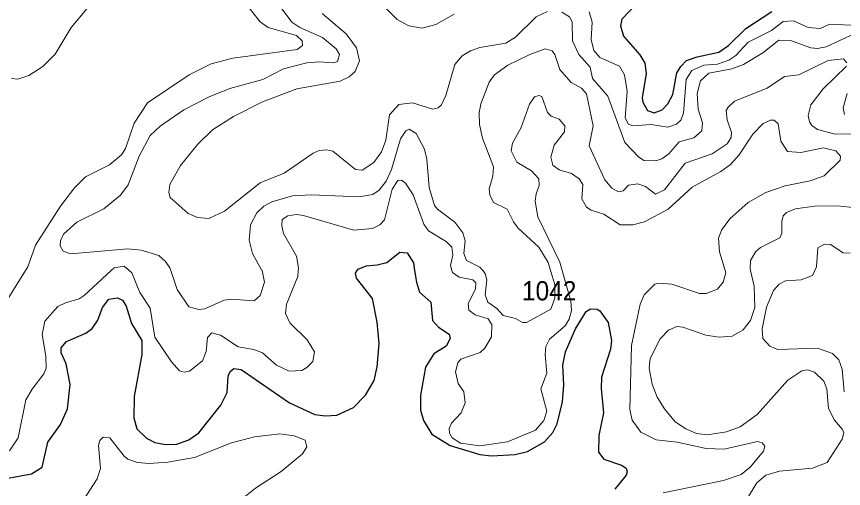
# Model space of a CAD drawing. Extents: x 473.9 to 500, y 7733.1 to 7760.8.
# Drawn here: x 479.07 to 482.505, y 7736.165 to 7738.123 of the extents above; entities that cross this region are included whole.
import ezdxf

# ---------------------------------------------------------------- set-up
doc = ezdxf.new("R2010")
doc.units = 0
doc.header["$LTSCALE"] = 0.032
doc.layers.add('1', color=7, linetype='Continuous', lineweight=25)
doc.layers.add('2', color=7, linetype='Continuous', lineweight=13)
doc.layers.add('21', color=7, linetype='Continuous')

msp = doc.modelspace()

# ---------------------------------------------------------------- linework, layer by layer
at = {"layer": '1'}
for points in [[(481.6836, 7738.2173), (481.5845, 7738.1126), (481.5783, 7738.0843), (481.5914, 7738.0411), (481.6589, 7737.9644), (481.6805, 7737.9299), (481.6856, 7737.8865), (481.6682, 7737.7858), (481.6714, 7737.7672), (481.6907, 7737.7335), (481.7191, 7737.723), (481.752, 7737.7356), (481.7753, 7737.7605), (481.7969, 7737.7999), (481.8131, 7737.8888), (481.8292, 7737.9156), (481.8536, 7737.9401), (481.8975, 7737.9558), (481.9874, 7737.9752), (482.0274, 7738.0025), (482.0988, 7738.0734), (482.2073, 7738.1445)], [(479.0279, 7736.2065), (479.1319, 7736.2254), (479.1762, 7736.2532), (479.2, 7736.3575), (479.2534, 7736.4312), (479.2818, 7736.4958), (479.2929, 7736.5965), (479.2765, 7736.6821), (479.2555, 7736.7281), (479.2563, 7736.7484), (479.278, 7736.7748), (479.3583, 7736.8092), (479.385, 7736.8293), (479.4086, 7736.8633), (479.4273, 7736.9165), (479.4538, 7736.9502), (479.4901, 7736.9566), (479.5103, 7736.9457), (479.5261, 7736.9215), (479.5472, 7736.8501), (479.5903, 7736.7797), (479.5906, 7736.7216), (479.5587, 7736.5466), (479.5578, 7736.4584), (479.5701, 7736.4119), (479.6103, 7736.3742), (479.6445, 7736.3563), (479.6888, 7736.3475), (479.7356, 7736.3487), (479.7858, 7736.3668), (479.8281, 7736.3961), (479.9187, 7736.5101), (479.9449, 7736.5639), (479.9495, 7736.6311), (479.9573, 7736.651), (479.9725, 7736.6633), (480.0028, 7736.6593), (480.204, 7736.5202), (480.3093, 7736.4727), (480.3538, 7736.4663), (480.4009, 7736.4695), (480.4693, 7736.5013), (480.5199, 7736.5526), (480.5553, 7736.6126), (480.5681, 7736.6704), (480.5763, 7736.7663), (480.5686, 7736.8556), (480.5482, 7736.9528), (480.4826, 7737.0374), (480.4785, 7737.0585), (480.4854, 7737.0693), (480.4891, 7737.0751), (480.5227, 7737.0888), (480.5688, 7737.0923), (480.6088, 7737.1026), (480.6618, 7737.1449), (480.6923, 7737.1425), (480.7188, 7737.1017), (480.7238, 7737.0693), (480.7311, 7737.0214), (480.7444, 7736.9796), (480.7907, 7736.9376), (480.7981, 7736.8622), (480.8233, 7736.835), (480.8667, 7736.8049), (480.8718, 7736.7873), (480.855, 7736.7557), (480.8037, 7736.7234), (480.7693, 7736.6684), (480.7483, 7736.5525), (480.7476, 7736.4907), (480.7606, 7736.4465), (480.7958, 7736.3899)], [(480.7958, 7736.3899), (480.8718, 7736.3434), (480.9953, 7736.3064), (481.0435, 7736.2999), (481.1413, 7736.3063), (481.1927, 7736.3181), (481.2629, 7736.3583), (481.2976, 7736.3968), (481.3165, 7736.4329), (481.3385, 7736.5247), (481.3431, 7736.5953), (481.3388, 7736.6768), (481.3504, 7736.7319), (481.3926, 7736.827), (481.4365, 7736.8987), (481.4536, 7736.91), (481.4817, 7736.9094), (481.4928, 7736.9027), (481.5278, 7736.8544), (481.5411, 7736.7792), (481.5377, 7736.7429), (481.5002, 7736.6267), (481.498, 7736.5805), (481.5088, 7736.4794), (481.4894, 7736.3845), (481.4874, 7736.3161), (481.5095, 7736.2867), (481.5832, 7736.2616), (481.6028, 7736.2489), (481.607, 7736.2345), (481.6029, 7736.2198), (481.5553, 7736.162)]]:
    msp.add_lwpolyline(points, dxfattribs=at)
at = {"layer": '2'}
for points in [[(480.8878, 7738.1326), (480.8115, 7738.0898), (480.7547, 7738.0743), (480.6995, 7738.0844), (480.6516, 7738.1106), (480.532, 7738.2302)], [(479.2957, 7737.1391), (479.2645, 7737.1502), (479.2516, 7737.1717), (479.2524, 7737.1923), (479.266, 7737.2202), (479.3204, 7737.2702), (479.4336, 7737.3252), (479.5016, 7737.3824), (479.5334, 7737.4247), (479.5798, 7737.5431), (479.626, 7737.6301), (479.6663, 7737.6678), (479.7648, 7737.7359), (479.8707, 7737.7897), (479.9566, 7737.824), (480.0933, 7737.8618), (480.1791, 7737.9062), (480.2755, 7737.9311), (480.3291, 7737.9352), (480.3865, 7737.9304), (480.403, 7737.9366), (480.4111, 7737.9662), (480.3981, 7737.9887), (480.3405, 7738.0364), (480.2466, 7738.0775), (480.2137, 7738.1001), (480.165, 7738.1642)], [(480.0253, 7738.173), (480.0818, 7738.1008), (480.1152, 7738.0776), (480.2337, 7738.0445), (480.2561, 7738.0221), (480.2578, 7738.0024), (480.2356, 7737.9864), (479.9687, 7737.9497), (479.8789, 7737.9272), (479.7873, 7737.8814), (479.6144, 7737.7644)], [(479.0491, 7737.8656), (479.0757, 7737.8637), (479.122, 7737.8779), (479.1799, 7737.9155), (479.2301, 7737.9675), (479.2975, 7738.0779), (479.3628, 7738.1546)], [(480.3403, 7738.1358), (480.4388, 7738.0516), (480.4823, 7737.9931), (480.4951, 7737.9395), (480.4774, 7737.8956), (480.4525, 7737.8732), (480.4144, 7737.8544), (480.2343, 7737.8227), (480.0922, 7737.7695), (479.9717, 7737.7083), (479.8836, 7737.6524), (479.8231, 7737.593), (479.7508, 7737.5055), (479.7075, 7737.4256), (479.7023, 7737.3924), (479.709, 7737.3729), (479.7833, 7737.3055), (479.8226, 7737.2894), (479.8693, 7737.2854), (479.9342, 7737.3158), (480.0825, 7737.4326), (480.1816, 7737.4726), (480.3019, 7737.5558), (480.327, 7737.5669), (480.3586, 7737.5701), (480.3839, 7737.565), (480.4786, 7737.4879), (480.5062, 7737.4861), (480.5549, 7737.5175), (480.5863, 7737.5624), (480.6042, 7737.6106), (480.6201, 7737.7147), (480.658, 7737.758), (480.7151, 7737.7654), (480.7989, 7737.7384), (480.8211, 7737.7442), (480.8352, 7737.7562), (480.8529, 7737.7961), (480.8901, 7737.9237), (480.9212, 7737.9594), (480.9564, 7737.9809), (480.9943, 7737.9945), (481.1031, 7738.0129), (481.1426, 7738.0376), (481.2288, 7738.1211), (481.2757, 7738.1433)], [(481.3347, 7738.1416), (481.3673, 7738.1217), (481.3778, 7738.1005), (481.3795, 7738.0224), (481.4056, 7737.9654)], [(481.4489, 7738.142), (481.4607, 7738.0995), (481.4576, 7738.028), (481.4682, 7737.9821), (481.4933, 7737.9524), (481.5747, 7737.9167), (481.5961, 7737.8818), (481.6062, 7737.8121), (481.5982, 7737.7032), (481.6123, 7737.6766), (481.63, 7737.67), (481.7066, 7737.6754), (481.7761, 7737.6634)], [(481.7761, 7737.6634), (481.8112, 7737.6759), (481.8293, 7737.6936), (481.8401, 7737.7221), (481.8518, 7737.8618), (481.8747, 7737.8992), (481.9252, 7737.9206), (481.9814, 7737.926), (482.0282, 7737.9417), (482.0576, 7737.9613), (482.1092, 7738.0166), (482.2062, 7738.0653), (482.2544, 7738.1019), (482.2974, 7738.1054), (482.3585, 7738.0774), (482.4079, 7738.074), (482.4469, 7738.091), (482.5939, 7738.0848)], [(481.4056, 7737.9654), (481.4532, 7737.9134), (481.4628, 7737.8663), (481.5259, 7737.7924), (481.5968, 7737.601), (481.654, 7737.5408), (481.6754, 7737.5262), (481.7255, 7737.5242), (481.7505, 7737.5326), (481.7801, 7737.5537), (481.8228, 7737.6027), (481.8838, 7737.6198), (481.9169, 7737.6493), (481.9189, 7737.6819), (481.9018, 7737.7393), (481.8973, 7737.8041), (481.9111, 7737.8562), (481.9451, 7737.888), (482.0411, 7737.9063), (482.0898, 7737.9247), (482.1697, 7737.9731), (482.2365, 7738.025), (482.285, 7738.0242), (482.3692, 7737.9931), (482.3974, 7737.9898), (482.4335, 7737.9973), (482.5525, 7738.0533)], [(482.0382, 7737.6218), (482.0225, 7737.5944), (481.9597, 7737.5536), (481.8477, 7737.515), (481.7622, 7737.4045), (481.7238, 7737.3861), (481.6825, 7737.4183), (481.6503, 7737.4286), (481.6122, 7737.4239), (481.5905, 7737.4001), (481.57, 7737.396), (481.5425, 7737.411), (481.5133, 7737.4459), (481.4482, 7737.5868), (481.4654, 7737.669), (481.438, 7737.8025), (481.4174, 7737.8258), (481.3746, 7737.849), (481.3269, 7737.9028), (481.3063, 7737.966), (481.295, 7737.9809), (481.2653, 7737.9888), (481.2022, 7737.966), (481.1114, 7737.9207), (481.055, 7737.881), (481.0331, 7737.8512), (480.9981, 7737.7613), (480.9919, 7737.7232), (480.9934, 7737.6749), (481.0061, 7737.6187), (481.0513, 7737.4993), (481.0481, 7737.4605), (481.0338, 7737.4085), (481.0355, 7737.3838), (481.0514, 7737.3518), (481.108, 7737.3238), (481.1338, 7737.2714), (481.1542, 7737.2447), (481.2399, 7737.1669), (481.278, 7737.103), (481.2882, 7737.0693), (481.3056, 7737.0113), (481.3055, 7736.9541), (481.289, 7736.9085), (481.1883, 7736.854), (481.1714, 7736.8537), (481.1424, 7736.8705), (481.0917, 7736.8821), (481.0658, 7736.9124), (481.0272, 7736.9381), (481.0161, 7736.9679), (481.0239, 7737.0306), (481.0174, 7737.0569), (481.0071, 7737.0693), (480.9949, 7737.0838), (480.9393, 7737.1109), (480.9277, 7737.1395), (480.934, 7737.1923), (480.9244, 7737.2262), (480.8914, 7737.2702), (480.8184, 7737.3242), (480.807, 7737.3387), (480.7845, 7737.4133), (480.7741, 7737.5318), (480.7643, 7737.5725), (480.7301, 7737.6373), (480.7017, 7737.6552), (480.6866, 7737.649), (480.6655, 7737.616), (480.6278, 7737.4879), (480.6059, 7737.4406), (480.5763, 7737.4031), (480.5505, 7737.3853), (480.4921, 7737.3748), (480.2953, 7737.3829), (480.2164, 7737.3789), (480.1303, 7737.3544), (480.0977, 7737.3363), (480.0689, 7737.308), (480.0424, 7737.259), (480.0371, 7737.1952), (480.05, 7737.14), (480.0896, 7737.0693), (480.0899, 7737.0688), (480.1002, 7737.0205), (480.0822, 7736.9658), (480.057, 7736.9439), (479.9619, 7736.951), (479.9324, 7736.9465), (479.8521, 7736.9108), (479.8279, 7736.907), (479.7858, 7736.9187), (479.7373, 7736.991), (479.7109, 7737.0693), (479.7073, 7737.08), (479.6893, 7737.1071), (479.6609, 7737.1316), (479.5883, 7737.1534), (479.5331, 7737.1594), (479.2957, 7737.1391)], [(482.5184, 7737.931), (482.5048, 7737.948), (482.4415, 7737.9405), (482.3193, 7737.8806), (482.26, 7737.8746), (482.1884, 7737.8264), (482.052, 7737.7724), (482.0254, 7737.7477), (482.0179, 7737.7327), (482.0224, 7737.6942), (482.0404, 7737.6423), (482.0382, 7737.6218)], [(482.5788, 7737.6361), (482.4708, 7737.6351), (482.3976, 7737.655), (482.374, 7737.6703), (482.3636, 7737.6856), (482.358, 7737.713), (482.3696, 7737.7569), (482.4206, 7737.8233), (482.517, 7737.917)], [(480.7174, 7737.3839), (480.7614, 7737.2611), (480.7812, 7737.2334), (480.8549, 7737.1903), (480.8785, 7737.1658), (480.8819, 7737.1337), (480.8721, 7737.0907), (480.8789, 7737.0693), (480.8816, 7737.0609), (480.9088, 7737.0421), (480.9657, 7737.0314), (480.9776, 7737.018), (480.9773, 7736.9937), (480.9464, 7736.9316), (480.9493, 7736.9049), (480.9748, 7736.8857), (481.0294, 7736.8686), (481.0449, 7736.8458), (481.0437, 7736.7943), (481.0156, 7736.7472), (480.9964, 7736.7296), (480.916, 7736.7013), (480.9032, 7736.6859), (480.8939, 7736.6495), (480.9045, 7736.6007), (480.928, 7736.566), (480.9341, 7736.5199), (480.9173, 7736.4796), (480.8768, 7736.4362), (480.8673, 7736.4143), (480.8686, 7736.395), (480.8802, 7736.3747), (480.9139, 7736.3531), (480.9948, 7736.3425), (481.1089, 7736.3588), (481.2258, 7736.4067), (481.2599, 7736.4468), (481.2723, 7736.4855), (481.2484, 7736.5782), (481.2726, 7736.6431), (481.2653, 7736.7209), (481.2683, 7736.7536), (481.2846, 7736.7846), (481.3488, 7736.8392), (481.3655, 7736.8676), (481.3748, 7736.9036), (481.372, 7736.9427), (481.3363, 7737.0693), (481.3265, 7737.1041), (481.2353, 7737.2922), (481.2251, 7737.3566), (481.2282, 7737.3871), (481.2405, 7737.4214), (481.24, 7737.4492), (481.2088, 7737.4824), (481.1486, 7737.5188), (481.1246, 7737.5661), (481.1306, 7737.5974), (481.1663, 7737.6627), (481.2006, 7737.7601), (481.2221, 7737.7903), (481.2399, 7737.7961), (481.2522, 7737.7918), (481.2754, 7737.7249), (481.2914, 7737.7095), (481.3247, 7737.697), (481.3479, 7737.6692), (481.3467, 7737.6443), (481.304, 7737.5892), (481.2894, 7737.5394), (481.2984, 7737.5068), (481.3236, 7737.4866), (481.3754, 7737.4712), (481.4075, 7737.4501), (481.422, 7737.426), (481.4186, 7737.367), (481.4375, 7737.3328), (481.4574, 7737.3204), (481.5099, 7737.3034), (481.5769, 7737.2586), (481.63, 7737.2589), (481.6783, 7737.2715), (481.7763, 7737.3237), (481.8763, 7737.4157), (481.9951, 7737.4796), (482.0352, 7737.5088), (482.0723, 7737.5486), (482.128, 7737.6354), (482.1713, 7737.6796), (482.2014, 7737.6937), (482.2173, 7737.6934), (482.2335, 7737.6782), (482.2442, 7737.6058), (482.2728, 7737.5633), (482.3277, 7737.5596), (482.4222, 7737.5781), (482.4736, 7737.5662), (482.4927, 7737.544), (482.4913, 7737.5273), (482.4243, 7737.4628)], [(482.521, 7737.8035), (482.5043, 7737.7436), (482.5094, 7737.7166)], [(479.6144, 7737.7644), (479.5584, 7737.6803), (479.5232, 7737.5751), (479.5068, 7737.5493), (479.4564, 7737.5081), (479.3574, 7737.4584), (479.3114, 7737.4117), (479.2533, 7737.3365), (479.1496, 7737.1748), (479.1166, 7737.0848), (479.1069, 7737.0693), (479.0253, 7736.9381)], [(479.0405, 7736.3215), (479.0767, 7736.3747), (479.1095, 7736.5327), (479.135, 7736.5777), (479.1837, 7736.6406), (479.193, 7736.6646), (479.1924, 7736.7145), (479.1765, 7736.8044), (479.1882, 7736.8596), (479.2425, 7736.9195), (479.2732, 7736.9356), (479.33, 7736.9519), (479.3517, 7736.9654), (479.4638, 7737.0693), (479.4761, 7737.0807), (479.5169, 7737.0879), (479.5384, 7737.0693), (479.549, 7737.0601), (479.5822, 7736.9782), (479.6251, 7736.9127), (479.6448, 7736.7932), (479.7141, 7736.6906), (479.7478, 7736.6531), (479.7663, 7736.6472), (479.7893, 7736.6525), (479.8432, 7736.6943), (479.8578, 7736.7332), (479.863, 7736.7921), (479.8816, 7736.8104), (479.918, 7736.8018), (479.9909, 7736.7526), (480.0563, 7736.7413), (480.0917, 7736.7278), (480.1503, 7736.6765), (480.2023, 7736.6512), (480.2551, 7736.6547), (480.2767, 7736.6669), (480.3013, 7736.692), (480.3078, 7736.7315), (480.2778, 7736.7819), (480.2053, 7736.8526), (480.1881, 7736.8913), (480.1912, 7736.9304), (480.2391, 7737.0446), (480.2403, 7737.0693), (480.2409, 7737.0811), (480.2329, 7737.1287), (480.1796, 7737.2231), (480.1718, 7737.2542), (480.1743, 7737.2808), (480.1972, 7737.2961), (480.2329, 7737.3016), (480.2626, 7737.298), (480.4717, 7737.2374), (480.5488, 7737.2438), (480.5791, 7737.2584), (480.5986, 7737.28), (480.6302, 7737.4073), (480.6537, 7737.4433), (480.6692, 7737.4441), (480.6852, 7737.4313), (480.7174, 7737.3839)], [(482.4243, 7737.4628), (482.3665, 7737.4413), (482.2625, 7737.4213), (482.1821, 7737.3929), (482.1091, 7737.3518), (482.034, 7737.2855), (482, 7737.2391), (481.9863, 7737.2033), (481.9895, 7737.147), (482.0139, 7737.0693), (482.0169, 7737.0596), (482.0055, 7737.0205), (481.9812, 7736.9918), (481.935, 7736.9744), (481.9065, 7736.9747), (481.7915, 7737.0128), (481.7388, 7737.0175), (481.7211, 7737.013), (481.6771, 7736.9691), (481.6599, 7736.9304), (481.625, 7736.7584), (481.6182, 7736.4925), (481.6268, 7736.4491), (481.6633, 7736.3988), (481.7265, 7736.3665), (481.8139, 7736.357), (481.9351, 7736.3312), (482.0101, 7736.3281), (482.1483, 7736.3601), (482.1677, 7736.3552), (482.1788, 7736.341), (482.173, 7736.3195), (482.1187, 7736.2544), (482.0802, 7736.223), (482.0068, 7736.1976), (481.756, 7736.1476)], [(482.0994, 7736.1145), (482.1453, 7736.1891), (482.1831, 7736.2205), (482.2395, 7736.2364), (482.3767, 7736.249), (482.4374, 7736.2734), (482.4999, 7736.3692), (482.5066, 7736.3964), (482.5015, 7736.4102), (482.4682, 7736.4487), (482.4426, 7736.4963), (482.436, 7736.5783), (482.4238, 7736.6109), (482.3853, 7736.6472), (482.3555, 7736.6577), (482.3325, 7736.6537), (482.2735, 7736.6148), (482.1468, 7736.4723), (482.0759, 7736.421), (482.0196, 7736.4006), (481.9393, 7736.3875), (481.8948, 7736.3931), (481.8498, 7736.4124), (481.8066, 7736.4418), (481.7613, 7736.4958), (481.7312, 7736.544), (481.7107, 7736.5981), (481.6979, 7736.6646), (481.7017, 7736.7048), (481.7437, 7736.7862), (481.7785, 7736.8216), (481.8123, 7736.8368), (481.8376, 7736.8343), (481.9335, 7736.8016), (481.988, 7736.7927), (482.0427, 7736.7968), (482.0883, 7736.8231), (482.1183, 7736.8618), (482.1369, 7736.9155), (482.1344, 7737.0039), (482.1191, 7737.0693), (482.1176, 7737.0757), (482.1193, 7737.1114), (482.141, 7737.1477), (482.1598, 7737.1652), (482.2401, 7737.2043), (482.2493, 7737.2247), (482.2486, 7737.2729), (482.2542, 7737.296), (482.2678, 7737.3104), (482.3064, 7737.3248), (482.3847, 7737.3362), (482.479, 7737.3379), (482.7155, 7737.3129)], [(482.5326, 7737.1412), (482.504, 7737.1434), (482.4507, 7737.177), (482.4266, 7737.1784), (482.3985, 7737.1629), (482.3932, 7737.0842), (482.3863, 7737.0693), (482.3767, 7737.0486), (482.3294, 7737.0312), (482.2636, 7737.0259), (482.2385, 7737.0126), (482.2146, 7736.9866), (482.1849, 7736.9176), (482.167, 7736.827), (482.1705, 7736.7868), (482.1989, 7736.7558), (482.232, 7736.7423), (482.3965, 7736.7476), (482.4593, 7736.7251), (482.4861, 7736.6992), (482.5002, 7736.6603), (482.508, 7736.5654)], [(479.993, 7736.1112), (480.0625, 7736.1661), (480.1688, 7736.2362), (480.2578, 7736.3086), (480.2767, 7736.3376), (480.2685, 7736.3655), (480.2235, 7736.3832), (480.1635, 7736.3914), (480.059, 7736.3794), (479.963, 7736.354), (479.8096, 7736.2931), (479.6982, 7736.2743), (479.6215, 7736.2693), (479.5733, 7736.2727), (479.5321, 7736.2872), (479.5169, 7736.2988), (479.4581, 7736.3756), (479.4295, 7736.3783), (479.4163, 7736.3644), (479.4105, 7736.344), (479.4193, 7736.2486), (479.4055, 7736.2057), (479.3036, 7736.0494)]]:
    msp.add_lwpolyline(points, dxfattribs=at)

# ---------------------------------------------------------------- texts
at = {"layer": '21', "width": 0.95}
msp.add_text('1042', height=0.08, dxfattribs=at).set_placement((481.1696, 7736.9453))

doc.saveas('drawing.dxf')
